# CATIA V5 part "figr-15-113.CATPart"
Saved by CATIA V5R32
Part number: Part1
Bounding box of the stored display mesh (mm): x -55.37 to 68.649, y -21.457 to 35.984, z 0 to 57.441
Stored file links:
  D:\PROJECTS\Project 2022\CATIA V5 6R 2022\Resources\Part Files\c15_catia_v5_6r2022_prt\figr-15-113.CATPart
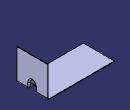
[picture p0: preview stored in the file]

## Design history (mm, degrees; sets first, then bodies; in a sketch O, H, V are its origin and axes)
SheetMetalParameters1: Thickness 1, BendRadius 2, KFactor 0.400515 {= log(min(100,max(20*SheetMetalParameters1.BendRadius,SheetMetalParameters1.Thickness)/SheetMetalParameters1.Thickness))/log(100)/2}, ReliefRadialLength 1, ReliefAxialLength 2, MinimumBendRadius 0
Body1 (main body)
  Sketch1 on xy-plane, origin (0, 0, 0), H (1, 0, 0), V (0, 1, 0)
    line L1 (-55.3695, 35.9836) -> (67.649, 35.9836)
    line L2 (67.649, 35.9836) -> (67.649, -21.4575)
    line L3 (67.649, -21.4575) -> (-55.3695, -21.4575)
    line L4 (-55.3695, -21.4575) -> (-55.3695, 35.9836)
    horizontal: L1 H, L3 H
    vertical: L2 V, L4 V
  Wall1: Thickness 1, Profile Sketch1
  d_NewWallOnEdge1: NewWallOnEdge_Edge edge [face of Wall1 | face of Wall1], NewWallOnEdge_Length 57.4411, NewWallOnEdge_HeightLimitOffset 0, NewWallOnEdge_WidthOffset1 0, NewWallOnEdge_WidthOffset2 0, NewWallOnEdge_Angle 90, NewWallOnEdge_BendRadiusValue 2 {= SheetMetalParameters1.BendRadius}, NewWallOnEdge_BendTable SheetMetalParameters1, KFacteur 0.400515 {= log(min(100,max(20*d_NewWallOnEdge1.Radius,SheetMetalParameters1.Thickness)/SheetMetalParameters1.Thickness))/log(100)/2}
  Sketch2 on , origin (67.7759, 6.9809, 0.8843), H (0.7052, 0, 0.709), V (0, -1, 0)
    point P1 (0, 0)
  d_Stamp1: Stamp_FilletRadius 2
